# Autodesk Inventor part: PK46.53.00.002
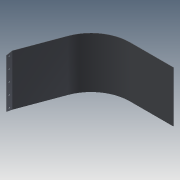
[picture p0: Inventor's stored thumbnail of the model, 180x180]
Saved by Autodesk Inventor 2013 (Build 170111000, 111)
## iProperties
Created: 2005-03
Part Number: PK46.53.00.002
Material: Steel, Mild
Document SubType Name: Обычные детали
Designer: HKostja
Manufacturer: Standard
Standards Organization: Custom
Density: 7.86 g/cm^3
Sheet Metal Rule: По умолчанию
Mass: 16132.9 g
Surface Area: 13800.9 cm^2
Volume: 2052.54 cm^3
Author: HKostja
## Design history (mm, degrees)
node "ФлнОтгиб1"
sketch "Эскиз2" dims "d25" = 10
  geometry: L1 (0, 0)-(500, 0) reference; L2 (0, 54.461)-(0, 0) reference; L3 (500, 0)-(500, 54.461) reference; L4 (490, 0)-(500, 55); L5 (10, 0)-(0, 55); L6 (500, 55)-(500, 54.461); L7 (0, 55)-(0, 54.461); C1 r 6 at (30, 25); C2 r 6 at (140, 25); C3 r 6 at (250, 25); C4 r 6 at (360, 25); C5 r 6 at (470, 25)
  constraints: 8 end point, 5 centre point, 4 point on line, 1 collinear, 1 horizontal, 8 other
  dimensions: "d17" = 12 diameter of C1; "d18" = 30 distance from line of C1.centre L2; "d19" = 25 distance from line of C1.centre L1; "d22" = 110 distance of C1.centre C2.centre; "d27" = 30 horizontal distance of C5.centre L1.end (derived); "d30" = 10 distance from line of L3 L4.start; "d31" = 10 distance from line of L2 L5.start (= d30); "d32" = 55 distance from line of L1 L5.end; "d33" = 55 distance from line of L1 L4.end (= d32)
extrude "Выдавливание2" cut sketch "Эскиз2" stored distance "d28" = 10; taper "d29" = 0 deg
body "Solid1"
sketch "Эскиз1"
  geometry: L1 (264.331, 0)-(690, 0); L2 (-240, -646.916)-(-91.941, -247.826); L3 (-240, -646.916)-(-240, -701.916); A1 r 380 centre (264.331, -380) between (264.331, 0) and (-91.941, -247.826); 1 further point
  constraints: 6 end point, 2 point on circle, 2 point on line, 2 tangent, 1 centre point, 1 equal length, 1 horizontal, 1 perpendicular, 1 other
  dimensions: "d0" = 690 distance of point (0, 0) L1.end; "d3" = 240 horizontal distance of point (0, 0) L2.start; "d6" = 380 radius of A1; "d9" = 55 distance of L2.start L3.end
feature "Плакирование1" dims "d10" = 500, "d11" = 3 (= Ширина_просечки), "d13" = 6 (= Минимальный_остаток), "d15" = 3 (= Радиус_гибки), "d16" = 3, "Толщина" = 3
feature "Изгиб1" dims "d11" = 3 (= Ширина_просечки), "d12" = 1.5 (= Глубина_просечки), "d13" = 6 (= Минимальный_остаток), "d14" = 3 (= Радиус_гибки), "d15" = 3 (= Радиус_гибки), "d16" = 3, "Толщина" = 3, "Зазор_стыка" = 0.01
other parameters: "Радиус_гибки" = 3 (= Толщина), "Ширина_просечки" = 3 (= Толщина), "Глубина_просечки" = 1.5 (= 0.5 x Толщина), "Размер_высечки" = 12 (= 4 x Толщина), "Минимальный_остаток" = 6 (= 2 x Толщина), "Радиус_перехода" = 3 (= Радиус_гибки), "JacobiRadiusSize" = 3 (= Толщина), "GapSize" = 3 (= Толщина)
